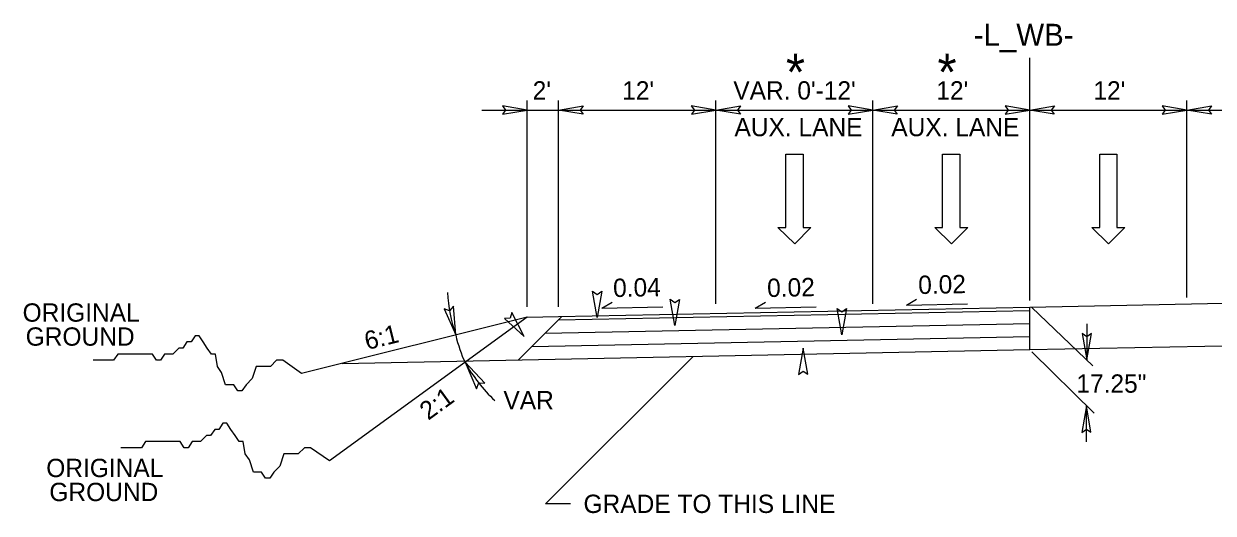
# Model space of a CAD drawing. Extents: x 1726790 to 1728895, y 539219 to 541550.
# Drawn here: x 1726942.3 to 1727397, y 540345.9 to 540533.1 of the extents above; entities that cross this region are included whole.
import ezdxf

# ---------------------------------------------------------------- set-up
doc = ezdxf.new("R2010")
doc.units = 0
for name, color, linetype in [('Default', 7, 'Continuous'), ('Prop Dimension Text', 7, 'Continuous'), ('Typical Hinge Slope Interstate CELL', 7, 'Continuous'), ('Typical Pavement Slope CELL', 7, 'Continuous'), ('Typical Pavement Slope Information CELL', 7, 'Continuous'), ('Typical Terminator CELL', 7, 'Continuous'), ('Typical Text Centerline CELL', 7, 'Continuous'), ('Typical Text General CELL', 7, 'Continuous')]:
    doc.layers.add(name, color=color, linetype=linetype)

msp = doc.modelspace()

# ---------------------------------------------------------------- linework, layer by layer
at = {"layer": 'Default'}
for p, q in [((1727326.84, 540427.18), (1727326.84, 540520.09)), ((1727134.69, 540424.78), (1727134.69, 540503.77)), ((1727146.69, 540424.78), (1727146.69, 540503.77)), ((1727146.69, 540424.78), (1727146.69, 540502.57)), ((1727206.85, 540425.98), (1727206.85, 540503.77)), ((1727266.79, 540425.98), (1727266.79, 540503.77)), ((1727326.84, 540427.18), (1727326.84, 540503.77)), ((1727386.88, 540428.38), (1727386.88, 540503.77)), ((1727117.43, 540500.07), (1727146.8, 540500.07)), ((1727146.8, 540500.07), (1727206.85, 540500.07)), ((1727206.96, 540500.07), (1727267.01, 540500.07)), ((1727266.9, 540500.07), (1727326.94, 540500.07)), ((1727326.94, 540500.07), (1727386.99, 540500.07)), ((1727386.99, 540500.07), (1727447.04, 540500.07)), ((1727233.58, 540455.17), (1727233.58, 540483.17)), ((1727233.58, 540483.17), (1727240.18, 540483.17)), ((1727240.18, 540483.17), (1727240.18, 540455.17)), ((1727293.52, 540455.17), (1727293.52, 540483.17)), ((1727293.52, 540483.17), (1727300.12, 540483.17)), ((1727300.12, 540483.17), (1727300.12, 540455.17)), ((1727353.57, 540455.17), (1727353.57, 540483.17)), ((1727353.57, 540483.17), (1727360.17, 540483.17)), ((1727360.17, 540483.17), (1727360.17, 540455.17)), ((1727236.98, 540448.87), (1727230.58, 540455.17)), ((1727230.58, 540455.17), (1727233.58, 540455.17)), ((1727243.18, 540455.17), (1727236.98, 540448.87)), ((1727240.18, 540455.17), (1727243.18, 540455.17)), ((1727296.92, 540448.87), (1727290.52, 540455.17)), ((1727290.52, 540455.17), (1727293.52, 540455.17)), ((1727303.12, 540455.17), (1727296.92, 540448.87)), ((1727300.12, 540455.17), (1727303.12, 540455.17)), ((1727356.97, 540448.87), (1727350.57, 540455.17)), ((1727350.57, 540455.17), (1727353.57, 540455.17)), ((1727363.17, 540455.17), (1727356.97, 540448.87)), ((1727360.17, 540455.17), (1727363.17, 540455.17)), ((1727327.66, 540424.6), (1727350.96, 540402.3)), ((1727348.61, 540418.3), (1727348.61, 540404.54)), ((1727327.66, 540407.66), (1727351.49, 540384.17)), ((1727348.49, 540373.13), (1727348.49, 540386.89))]:
    msp.add_line(p, q, dxfattribs=at)
for points in [[(1727125.31, 540498.46), (1727134.69, 540500.07), (1727125.25, 540501.74), (1727126.45, 540500.07)], [(1727156.07, 540498.46), (1727146.69, 540500.07), (1727156.13, 540501.74), (1727154.93, 540500.07)], [(1727197.47, 540498.46), (1727206.85, 540500.07), (1727197.42, 540501.74), (1727198.62, 540500.07)], [(1727216.23, 540498.46), (1727206.85, 540500.07), (1727216.28, 540501.74), (1727215.08, 540500.07)], [(1727257.41, 540498.46), (1727266.79, 540500.07), (1727257.36, 540501.74), (1727258.56, 540500.07)], [(1727276.17, 540498.46), (1727266.79, 540500.07), (1727276.22, 540501.74), (1727275.02, 540500.07)], [(1727317.46, 540498.46), (1727326.84, 540500.07), (1727317.41, 540501.74), (1727318.6, 540500.07)], [(1727336.21, 540498.46), (1727326.84, 540500.07), (1727336.27, 540501.74), (1727335.07, 540500.07)], [(1727377.51, 540498.46), (1727386.88, 540500.07), (1727377.45, 540501.74), (1727378.65, 540500.07)], [(1727396.26, 540498.46), (1727386.88, 540500.07), (1727396.31, 540501.74), (1727395.12, 540500.07)], [(1727102.93, 540424.07), (1727107.38, 540414.04), (1727106.58, 540425.05), (1727105.06, 540423.24)], [(1727118.47, 540395.62), (1727110.94, 540403.59), (1727115.35, 540393.48), (1727116.19, 540395.69)], [(1727118.47, 540395.62), (1727110.94, 540403.59), (1727115.35, 540393.48), (1727116.19, 540395.69)]]:
    msp.add_lwpolyline(points, close=True, dxfattribs=at)
at = {"layer": 'Typical Hinge Slope Interstate CELL'}
for points in [[(1727048.47, 540399.31), (1727041.25, 540404.38), (1727038.91, 540404.38), (1727036.58, 540402.05), (1727035.02, 540402.05), (1727032.68, 540402.05), (1727031.13, 540402.05), (1727029.57, 540397.36), (1727027.23, 540395.04), (1727025.67, 540392.69), (1727024.11, 540392.69), (1727022.56, 540395.04), (1727021, 540395.04), (1727019.44, 540395.04), (1727017.89, 540399.71), (1727016.33, 540402.05), (1727015.55, 540406.73), (1727013.99, 540406.73), (1727012.43, 540409.05), (1727010.88, 540411.4), (1727009.32, 540413.74), (1727007.76, 540413.74), (1727006.2, 540411.4), (1727004.65, 540411.4), (1727003.09, 540409.05), (1727001.53, 540409.05), (1726999.19, 540406.73), (1726997.64, 540406.73), (1726996.08, 540406.73), (1726994.52, 540404.38), (1726992.96, 540404.38), (1726991.41, 540406.73), (1726989.85, 540406.73), (1726988.29, 540406.73), (1726986.74, 540406.73), (1726985.18, 540406.73), (1726982.84, 540406.73), (1726980.51, 540406.73), (1726978.17, 540406.73), (1726976.61, 540404.38), (1726974.28, 540404.38), (1726971.94, 540404.38), (1726968.82, 540404.38)], [(1727059.08, 540365.87), (1727051.86, 540370.94), (1727049.52, 540370.94), (1727047.19, 540368.61), (1727045.63, 540368.61), (1727043.29, 540368.61), (1727041.73, 540368.61), (1727040.18, 540363.92), (1727037.84, 540361.6), (1727036.28, 540359.25), (1727034.72, 540359.25), (1727033.17, 540361.6), (1727031.61, 540361.6), (1727030.05, 540361.6), (1727028.49, 540366.27), (1727026.94, 540368.61), (1727026.15, 540373.29), (1727024.6, 540373.29), (1727023.04, 540375.61), (1727021.48, 540377.96), (1727019.93, 540380.3), (1727018.37, 540380.3), (1727016.81, 540377.96), (1727015.25, 540377.96), (1727013.7, 540375.61), (1727012.14, 540375.61), (1727009.8, 540373.29), (1727008.24, 540373.29), (1727006.69, 540373.29), (1727005.13, 540370.94), (1727003.57, 540370.94), (1727002.01, 540373.29), (1727000.46, 540373.29), (1726998.9, 540373.29), (1726997.34, 540373.29), (1726995.79, 540373.29), (1726993.45, 540373.29), (1726991.11, 540373.29), (1726988.77, 540373.29), (1726987.22, 540370.94), (1726984.89, 540370.94), (1726982.55, 540370.94), (1726979.43, 540370.94)]]:
    msp.add_lwpolyline(points, dxfattribs=at)
for centre, start, end in [((1727164.55, 540433.38), 182.9343, 198.686), ((1727163.68, 540432.93), 209.0778, 226.6941), ((1727163.68, 540432.93), 209.0778, 226.6941)]:
    msp.add_arc(centre, 60.35, start, end, dxfattribs=at)
msp.add_ellipse((1727136.27, 540448.47), major_axis=(-9.27, -59.64), ratio=0.5, start_param=5.403228, end_param=5.638322, dxfattribs=at)
at = {"layer": 'Typical Pavement Slope CELL'}
for p, q in [((1727326.84, 540424.71), (1727561.06, 540429.4)), ((1727146.69, 540421.11), (1727326.81, 540424.71)), ((1727326.84, 540408.45), (1727326.84, 540424.71)), ((1727134.69, 540420.87), (1727048.47, 540399.31)), ((1727134.69, 540420.87), (1727059.08, 540365.87)), ((1727147.97, 540421.13), (1727131.38, 540404.54)), ((1727134.69, 540420.87), (1727146.69, 540421.11)), ((1727146.69, 540419.86), (1727326.84, 540423.46)), ((1727141.59, 540414.75), (1727326.84, 540418.46)), ((1727136.48, 540409.65), (1727326.84, 540413.45)), ((1727326.84, 540408.45), (1727561.09, 540413.13)), ((1727063.98, 540403.19), (1727326.84, 540408.45))]:
    msp.add_line(p, q, dxfattribs=at)
at = {"layer": 'Typical Pavement Slope Information CELL'}
for p, q in [((1727163.21, 540424.28), (1727167.13, 540426.65)), ((1727163.21, 540424.28), (1727186.52, 540424.75)), ((1727221.91, 540424.28), (1727225.82, 540426.65)), ((1727221.91, 540424.28), (1727245.22, 540424.75)), ((1727279.67, 540425.43), (1727283.58, 540427.8)), ((1727279.67, 540425.43), (1727302.98, 540425.9))]:
    msp.add_line(p, q, dxfattribs=at)
at = {"layer": 'Typical Terminator CELL'}
for p, q in [((1727141.67, 540349.49), (1727198.13, 540405.87)), ((1727151.23, 540349.49), (1727141.67, 540349.49))]:
    msp.add_line(p, q, dxfattribs=at)
for points in [[(1727163.25, 540430.8), (1727161.52, 540420.75), (1727159.73, 540430.86), (1727161.52, 540429.57)], [(1727192.87, 540427.67), (1727191.14, 540417.63), (1727189.35, 540427.73), (1727191.14, 540426.45)], [(1727256.74, 540424.13), (1727255.01, 540414.09), (1727253.23, 540424.19), (1727255.01, 540422.9)], [(1727126.08, 540420.39), (1727133.59, 540413.5), (1727128.83, 540422.59), (1727128.2, 540420.48)], [(1727346.88, 540414.59), (1727348.61, 540404.54), (1727350.4, 540414.65), (1727348.61, 540413.36)], [(1727241.98, 540399), (1727240.25, 540409.05), (1727238.46, 540398.95), (1727240.25, 540400.23)], [(1727350.22, 540376.85), (1727348.49, 540386.89), (1727346.71, 540376.79), (1727348.49, 540378.07)]]:
    msp.add_lwpolyline(points, close=True, dxfattribs=at)

# ---------------------------------------------------------------- texts
at = {"layer": 'Default'}
msp.add_text('17.25"', height=7.005, dxfattribs=at).set_placement((1727344.65, 540391.97))
at = {"layer": 'Prop Dimension Text'}
for s, p in [('ORIGINAL', (1726941.82, 540419.13)), ('GROUND', (1726943, 540409.95)), ('VAR', (1727125.62, 540385.63)), ('ORIGINAL', (1726950.86, 540359.7)), ('GROUND', (1726952.04, 540350.52))]:
    msp.add_text(s, height=7.005, dxfattribs=at).set_placement(p)
for s, rotation, p in [('6:1', 14.0362, (1727073.49, 540408.25)), ('2:1', 36.0298, (1727096.88, 540381.21))]:
    msp.add_text(s, height=7.005, rotation=rotation, dxfattribs=at).set_placement(p)
at = {"layer": 'Typical Pavement Slope Information CELL'}
for s, height, p in [('*', 14.01, (1727233.63, 540507.58)), ('*', 14.01, (1727291.57, 540507.58)), ("2'", 7.005, (1727136.81, 540504.08)), ("12'", 7.005, (1727171.01, 540504.08)), ("VAR. 0'-12'", 7.0055, (1727213.51, 540504.08)), ("12'", 7.005, (1727291.11, 540504.08)), ("12'", 7.005, (1727351.16, 540504.08)), ('AUX. LANE', 7.005, (1727213.96, 540490.06)), ('AUX. LANE', 7.005, (1727273.9, 540490.06))]:
    msp.add_text(s, height=height, dxfattribs=at).set_placement(p)
for s, p in [('0.04', (1727167.62, 540428.54)), ('0.02', (1727226.5, 540428.55)), ('0.02', (1727284.26, 540429.7))]:
    msp.add_text(s, height=7.005, rotation=1.1457, dxfattribs=at).set_placement(p)
at = {"layer": 'Typical Text Centerline CELL'}
msp.add_text('-L_WB-', height=8.421, dxfattribs=at).set_placement((1727305.41, 540524.63))
at = {"layer": 'Typical Text General CELL'}
msp.add_text('GRADE TO THIS LINE', height=7.0055, rotation=360, dxfattribs=at).set_placement((1727156.23, 540345.98))

doc.saveas('drawing.dxf')
